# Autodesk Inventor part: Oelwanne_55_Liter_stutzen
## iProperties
Created: 2005-05
Part Number: Oelwanne_55_Liter_stutzen
Material: Stahl (schweißbar)
Document SubType Name: Modeling
Designer: Mario Wipf
Manufacturer: Standard
Standards Organization: Custom
Author: Mario Wipf
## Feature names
1. Extrusion1
2. Bohrung1 [Hole]
